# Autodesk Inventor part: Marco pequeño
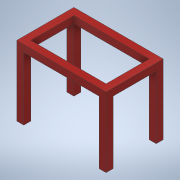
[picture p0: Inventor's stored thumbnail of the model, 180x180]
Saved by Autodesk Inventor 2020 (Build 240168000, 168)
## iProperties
Created: 2019-03
Part Number: Marco pequeño
Material: Generic
Document SubType Name: Modeling
Designer: user
Density: 1 g/cm^3
Appearance: Default
Author: user
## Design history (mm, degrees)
derived "Marco pequeño.iam"
body "Solid1"
node "Frame0001.iam:1::Skeleton0001.ipt:1"
node "Frame0001.iam:1::ANSI 1x1 00000001:1"
node "Frame0001.iam:1::ANSI 1x1 00000002:1"
node "Frame0001.iam:1::ANSI 1x1 00000003:1"
node "Frame0001.iam:1::ANSI 1x1 00000004:1"
node "Frame0001.iam:1::ANSI 1x1 00000005:1"
node "Frame0001.iam:1::ANSI 1x1 00000006:1"
node "Frame0001.iam:1::ANSI 1x1 00000007:1"
node "Frame0001.iam:1::ANSI 1x1 00000008:1"
other parameters: "G_L_1" = 204.737 [user parameter], "G_L_2" = 204.737 [user parameter]
